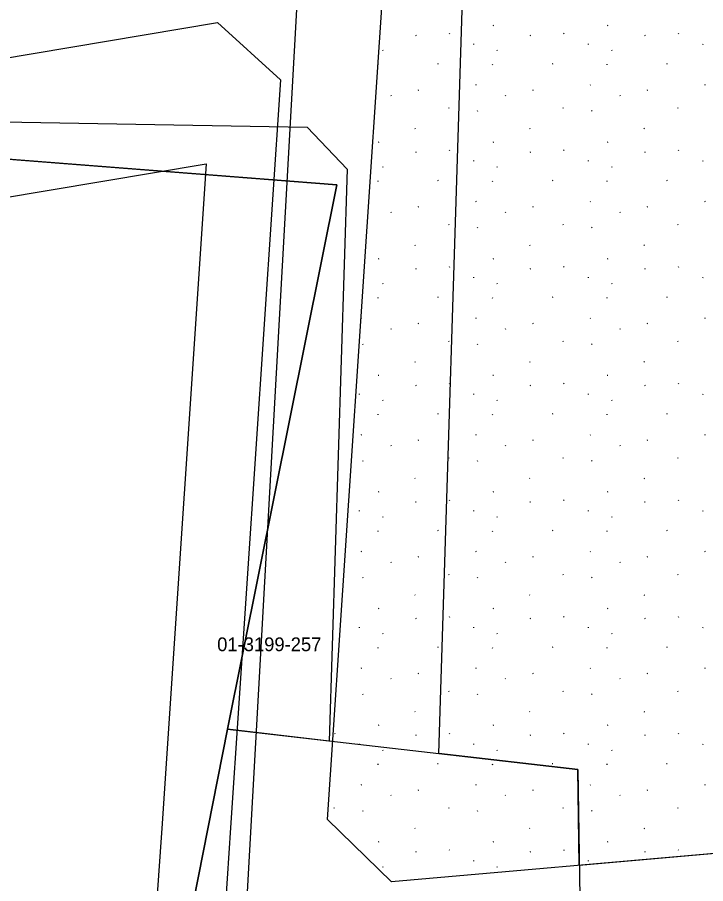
# Model space of a CAD drawing. Extents: x 419396 to 421519, y 4453567 to 4456767.
# Drawn here: x 420295.9 to 420346, y 4454723.5 to 4454786.6 of the extents above; entities that cross this region are included whole.
import ezdxf

# ---------------------------------------------------------------- set-up
doc = ezdxf.new("R2010")
doc.units = 0
for name, color, linetype in [('0_KADASTRO', 7, 'Continuous'), ('Level 20', 7, 'Continuous'), ('Level 29', 7, 'Continuous'), ('Level 41', 7, 'Continuous'), ('Level 9', 7, 'Continuous')]:
    doc.layers.add(name, color=color, linetype=linetype)

msp = doc.modelspace()

# ---------------------------------------------------------------- linework, layer by layer
at = {"layer": '0_KADASTRO'}
msp.add_lwpolyline([(420581.921, 4454746.454), (420336.793, 4454724.85), (420336.68, 4454731.82), (420326.57, 4454732.983), (420328.347, 4454789.429), (420328.423, 4454790.086), (420328.605, 4454790.721), (420328.89, 4454791.318), (420329.268, 4454791.859), (420329.731, 4454792.331), (420330.266, 4454792.72), (420330.857, 4454793.016), (420331.488, 4454793.21), (420432.926, 4454815.455)], dxfattribs=at)
for points in [[(420234.94, 4454775.21), (420237.99, 4454775.74), (420244.42, 4454776.89), (420251.07, 4454778.12), (420256.763, 4454779.251), (420319.17, 4454774.37), (420311.2, 4454734.75), (420308.37, 4454720.37), (420303.03, 4454697.63), (420301.63, 4454668.31), (420262.04, 4454668.65), (420253.019, 4454668.718), (420240.25, 4454669.24), (420238.25, 4454709.08), (420234.96, 4454774.88)], [(420268.759, 4454778.312), (420269.91, 4454779.388), (420317.003, 4454778.579), (420319.904, 4454775.525), (420318.591, 4454733.9), (420311.2, 4454734.75), (420319.17, 4454774.37)], [(420303.03, 4454697.63), (420308.37, 4454720.37), (420311.2, 4454734.75), (420336.68, 4454731.82), (420337.21, 4454699.26), (420323.81, 4454697.51), (420311.24, 4454697.29)]]:
    msp.add_lwpolyline(points, close=True, dxfattribs=at)
at = {"layer": 'Level 20'}
for p, q in [((420245.029, 4454765.083), (420309.65, 4454775.903)), ((420309.65, 4454775.903), (420306.439, 4454727.908)), ((420306.439, 4454727.908), (420305.299, 4454710.862))]:
    msp.add_line(p, q, dxfattribs=at)
at = {"layer": 'Level 29'}
for p, q in [((420318.485, 4454728.196), (420322.518, 4454788.474)), ((420241.237, 4454774.587), (420310.473, 4454786.18)), ((420310.473, 4454786.18), (420315.071, 4454782.017)), ((420315.071, 4454782.017), (420311.428, 4454727.574)), ((420426.15, 4454732.726), (420323.132, 4454723.646)), ((420323.132, 4454723.646), (420318.485, 4454728.196)), ((420311.428, 4454727.574), (420310.287, 4454710.528))]:
    msp.add_line(p, q, dxfattribs=at)
at = {"layer": 'Level 41'}
for p, q in [((420330.549, 4454785.976), (420330.502, 4454785.953)), ((420338.881, 4454785.976), (420338.834, 4454785.953)), ((420324.92, 4454785.247), (420324.873, 4454785.224)), ((420327.328, 4454785.411), (420327.356, 4454785.367)), ((420333.252, 4454785.247), (420333.205, 4454785.224)), ((420335.66, 4454785.411), (420335.688, 4454785.367)), ((420341.584, 4454785.247), (420341.537, 4454785.224)), ((420343.993, 4454785.411), (420344.021, 4454785.367)), ((420329.128, 4454784.582), (420329.135, 4454784.633)), ((420337.46, 4454784.582), (420337.467, 4454784.633)), ((420345.792, 4454784.582), (420345.8, 4454784.633)), ((420322.469, 4454784.196), (420322.497, 4454784.152)), ((420330.801, 4454784.196), (420330.829, 4454784.152)), ((420339.133, 4454784.196), (420339.161, 4454784.152)), ((420322.162, 4454783.108), (420322.17, 4454783.159)), ((420326.529, 4454783.182), (420326.482, 4454783.159)), ((420330.494, 4454783.108), (420330.502, 4454783.159)), ((420334.861, 4454783.182), (420334.815, 4454783.159)), ((420338.827, 4454783.108), (420338.834, 4454783.159)), ((420343.194, 4454783.182), (420343.147, 4454783.159)), ((420325.102, 4454781.253), (420325.055, 4454781.23)), ((420329.293, 4454781.648), (420329.246, 4454781.625)), ((420333.434, 4454781.253), (420333.387, 4454781.23)), ((420337.625, 4454781.648), (420337.578, 4454781.625)), ((420341.766, 4454781.253), (420341.719, 4454781.23)), ((420345.957, 4454781.648), (420345.91, 4454781.625)), ((420323.076, 4454780.9), (420323.104, 4454780.857)), ((420331.408, 4454780.9), (420331.437, 4454780.857)), ((420339.741, 4454780.9), (420339.769, 4454780.857)), ((420327.274, 4454779.997), (420327.302, 4454779.953)), ((420335.606, 4454779.997), (420335.634, 4454779.953)), ((420343.938, 4454779.997), (420343.966, 4454779.953)), ((420329.363, 4454779.777), (420329.391, 4454779.733)), ((420337.695, 4454779.777), (420337.723, 4454779.733)), ((420324.838, 4454778.501), (420324.866, 4454778.457)), ((420333.17, 4454778.501), (420333.198, 4454778.457)), ((420341.502, 4454778.501), (420341.53, 4454778.457)), ((420322.217, 4454777.488), (420322.17, 4454777.465)), ((420330.549, 4454777.488), (420330.502, 4454777.465)), ((420338.881, 4454777.488), (420338.834, 4454777.465)), ((420324.92, 4454776.759), (420324.873, 4454776.736)), ((420327.328, 4454776.922), (420327.356, 4454776.878)), ((420333.252, 4454776.759), (420333.205, 4454776.736)), ((420335.66, 4454776.922), (420335.688, 4454776.878)), ((420341.584, 4454776.759), (420341.537, 4454776.736)), ((420343.993, 4454776.922), (420344.021, 4454776.878)), ((420329.128, 4454776.093), (420329.135, 4454776.144)), ((420337.46, 4454776.093), (420337.467, 4454776.144)), ((420345.792, 4454776.093), (420345.8, 4454776.144)), ((420322.469, 4454775.707), (420322.497, 4454775.663)), ((420330.801, 4454775.707), (420330.829, 4454775.663)), ((420339.133, 4454775.707), (420339.161, 4454775.663)), ((420322.162, 4454774.619), (420322.17, 4454774.671)), ((420326.529, 4454774.694), (420326.482, 4454774.671)), ((420330.494, 4454774.619), (420330.502, 4454774.671)), ((420334.861, 4454774.694), (420334.815, 4454774.671)), ((420338.827, 4454774.619), (420338.834, 4454774.671)), ((420343.194, 4454774.694), (420343.147, 4454774.671)), ((420329.293, 4454773.159), (420329.246, 4454773.137)), ((420337.625, 4454773.159), (420337.578, 4454773.137)), ((420345.957, 4454773.159), (420345.91, 4454773.137)), ((420323.076, 4454772.412), (420323.104, 4454772.368)), ((420325.102, 4454772.764), (420325.055, 4454772.742)), ((420331.408, 4454772.412), (420331.437, 4454772.368)), ((420333.434, 4454772.764), (420333.387, 4454772.742)), ((420339.741, 4454772.412), (420339.769, 4454772.368)), ((420341.766, 4454772.764), (420341.719, 4454772.742)), ((420327.274, 4454771.508), (420327.302, 4454771.465)), ((420329.363, 4454771.288), (420329.391, 4454771.244)), ((420335.606, 4454771.508), (420335.634, 4454771.465)), ((420337.695, 4454771.288), (420337.723, 4454771.244)), ((420343.938, 4454771.508), (420343.966, 4454771.465)), ((420324.838, 4454770.012), (420324.866, 4454769.969)), ((420333.17, 4454770.012), (420333.198, 4454769.969)), ((420341.502, 4454770.012), (420341.53, 4454769.969)), ((420322.217, 4454768.999), (420322.17, 4454768.976)), ((420330.549, 4454768.999), (420330.502, 4454768.976)), ((420338.881, 4454768.999), (420338.834, 4454768.976)), ((420324.92, 4454768.27), (420324.873, 4454768.247)), ((420327.328, 4454768.433), (420327.356, 4454768.389)), ((420333.252, 4454768.27), (420333.205, 4454768.247)), ((420335.66, 4454768.433), (420335.688, 4454768.389)), ((420341.584, 4454768.27), (420341.537, 4454768.247)), ((420343.993, 4454768.433), (420344.021, 4454768.389)), ((420329.128, 4454767.604), (420329.135, 4454767.655)), ((420337.46, 4454767.604), (420337.467, 4454767.655)), ((420345.792, 4454767.604), (420345.8, 4454767.655)), ((420322.469, 4454767.218), (420322.497, 4454767.175)), ((420330.801, 4454767.218), (420330.829, 4454767.175)), ((420339.133, 4454767.218), (420339.161, 4454767.175)), ((420322.162, 4454766.131), (420322.17, 4454766.182)), ((420326.529, 4454766.205), (420326.482, 4454766.182)), ((420330.494, 4454766.131), (420330.502, 4454766.182)), ((420334.861, 4454766.205), (420334.815, 4454766.182)), ((420338.827, 4454766.131), (420338.834, 4454766.182)), ((420343.194, 4454766.205), (420343.147, 4454766.182)), ((420320.961, 4454764.671), (420320.924, 4454764.653)), ((420325.102, 4454764.276), (420325.055, 4454764.253)), ((420329.293, 4454764.671), (420329.246, 4454764.648)), ((420333.434, 4454764.276), (420333.387, 4454764.253)), ((420337.625, 4454764.671), (420337.578, 4454764.648)), ((420341.766, 4454764.276), (420341.719, 4454764.253)), ((420345.957, 4454764.671), (420345.91, 4454764.648)), ((420323.076, 4454763.923), (420323.104, 4454763.879)), ((420331.408, 4454763.923), (420331.437, 4454763.879)), ((420339.741, 4454763.923), (420339.769, 4454763.879)), ((420327.274, 4454763.019), (420327.302, 4454762.976)), ((420335.606, 4454763.019), (420335.634, 4454762.976)), ((420343.938, 4454763.019), (420343.966, 4454762.976)), ((420321.031, 4454762.799), (420321.059, 4454762.755)), ((420329.363, 4454762.799), (420329.391, 4454762.755)), ((420337.695, 4454762.799), (420337.723, 4454762.755)), ((420324.838, 4454761.523), (420324.866, 4454761.48)), ((420333.17, 4454761.523), (420333.198, 4454761.48)), ((420341.502, 4454761.523), (420341.53, 4454761.48)), ((420322.217, 4454760.51), (420322.17, 4454760.487)), ((420330.549, 4454760.51), (420330.502, 4454760.487)), ((420338.881, 4454760.51), (420338.834, 4454760.487)), ((420324.92, 4454759.781), (420324.873, 4454759.758)), ((420327.328, 4454759.944), (420327.356, 4454759.901)), ((420333.252, 4454759.781), (420333.205, 4454759.758)), ((420335.66, 4454759.944), (420335.688, 4454759.901)), ((420341.584, 4454759.781), (420341.537, 4454759.758)), ((420343.993, 4454759.944), (420344.021, 4454759.901)), ((420320.796, 4454759.115), (420320.803, 4454759.166)), ((420329.128, 4454759.115), (420329.135, 4454759.166)), ((420337.46, 4454759.115), (420337.467, 4454759.166)), ((420345.792, 4454759.115), (420345.8, 4454759.166)), ((420322.469, 4454758.729), (420322.497, 4454758.686)), ((420330.801, 4454758.729), (420330.829, 4454758.686)), ((420339.133, 4454758.729), (420339.161, 4454758.686)), ((420322.162, 4454757.642), (420322.17, 4454757.693)), ((420326.529, 4454757.716), (420326.482, 4454757.693)), ((420330.494, 4454757.642), (420330.502, 4454757.693)), ((420334.861, 4454757.716), (420334.815, 4454757.693)), ((420338.827, 4454757.642), (420338.834, 4454757.693)), ((420343.194, 4454757.716), (420343.147, 4454757.693)), ((420320.961, 4454756.182), (420320.914, 4454756.159)), ((420329.293, 4454756.182), (420329.246, 4454756.159)), ((420337.625, 4454756.182), (420337.578, 4454756.159)), ((420345.957, 4454756.182), (420345.91, 4454756.159)), ((420323.076, 4454755.434), (420323.104, 4454755.39)), ((420325.102, 4454755.787), (420325.055, 4454755.764)), ((420331.408, 4454755.434), (420331.437, 4454755.39)), ((420333.434, 4454755.787), (420333.387, 4454755.764)), ((420339.741, 4454755.434), (420339.769, 4454755.39)), ((420341.766, 4454755.787), (420341.719, 4454755.764)), ((420321.031, 4454754.31), (420321.059, 4454754.266)), ((420327.274, 4454754.531), (420327.302, 4454754.487)), ((420329.363, 4454754.31), (420329.391, 4454754.266)), ((420335.606, 4454754.531), (420335.634, 4454754.487)), ((420337.695, 4454754.31), (420337.723, 4454754.266)), ((420343.938, 4454754.531), (420343.966, 4454754.487)), ((420324.838, 4454753.035), (420324.866, 4454752.991)), ((420333.17, 4454753.035), (420333.198, 4454752.991)), ((420341.502, 4454753.035), (420341.53, 4454752.991)), ((420322.217, 4454752.021), (420322.17, 4454751.998)), ((420330.549, 4454752.021), (420330.502, 4454751.998)), ((420338.881, 4454752.021), (420338.834, 4454751.998)), ((420324.92, 4454751.292), (420324.873, 4454751.269)), ((420327.328, 4454751.455), (420327.356, 4454751.412)), ((420333.252, 4454751.292), (420333.205, 4454751.269)), ((420335.66, 4454751.455), (420335.688, 4454751.412)), ((420341.584, 4454751.292), (420341.537, 4454751.269)), ((420343.993, 4454751.455), (420344.021, 4454751.412)), ((420320.796, 4454750.626), (420320.803, 4454750.678)), ((420322.469, 4454750.241), (420322.497, 4454750.197)), ((420329.128, 4454750.626), (420329.135, 4454750.678)), ((420330.801, 4454750.241), (420330.829, 4454750.197)), ((420337.46, 4454750.626), (420337.467, 4454750.678)), ((420339.133, 4454750.241), (420339.161, 4454750.197)), ((420345.792, 4454750.626), (420345.8, 4454750.678)), ((420322.162, 4454749.153), (420322.17, 4454749.204)), ((420326.529, 4454749.227), (420326.482, 4454749.204)), ((420330.494, 4454749.153), (420330.502, 4454749.204)), ((420334.861, 4454749.227), (420334.815, 4454749.204)), ((420338.827, 4454749.153), (420338.834, 4454749.204)), ((420343.194, 4454749.227), (420343.147, 4454749.204)), ((420320.961, 4454747.693), (420320.914, 4454747.67)), ((420329.293, 4454747.693), (420329.246, 4454747.67)), ((420337.625, 4454747.693), (420337.578, 4454747.67)), ((420345.957, 4454747.693), (420345.91, 4454747.67)), ((420325.102, 4454747.298), (420325.055, 4454747.275)), ((420333.434, 4454747.298), (420333.387, 4454747.275)), ((420341.766, 4454747.298), (420341.719, 4454747.275)), ((420323.076, 4454746.945), (420323.104, 4454746.901)), ((420331.408, 4454746.945), (420331.437, 4454746.901)), ((420339.741, 4454746.945), (420339.769, 4454746.901)), ((420321.031, 4454745.821), (420321.059, 4454745.778)), ((420327.274, 4454746.042), (420327.302, 4454745.998)), ((420329.363, 4454745.821), (420329.391, 4454745.778)), ((420335.606, 4454746.042), (420335.634, 4454745.998)), ((420337.695, 4454745.821), (420337.723, 4454745.778)), ((420343.938, 4454746.042), (420343.966, 4454745.998)), ((420324.838, 4454744.546), (420324.866, 4454744.502)), ((420333.17, 4454744.546), (420333.198, 4454744.502)), ((420341.502, 4454744.546), (420341.53, 4454744.502)), ((420322.217, 4454743.532), (420322.17, 4454743.509)), ((420330.549, 4454743.532), (420330.502, 4454743.509)), ((420338.881, 4454743.532), (420338.834, 4454743.509)), ((420324.92, 4454742.803), (420324.873, 4454742.78)), ((420327.328, 4454742.967), (420327.356, 4454742.923)), ((420333.252, 4454742.803), (420333.205, 4454742.78)), ((420335.66, 4454742.967), (420335.688, 4454742.923)), ((420341.584, 4454742.803), (420341.537, 4454742.78)), ((420343.993, 4454742.967), (420344.021, 4454742.923)), ((420320.796, 4454742.138), (420320.803, 4454742.189)), ((420329.128, 4454742.138), (420329.135, 4454742.189)), ((420337.46, 4454742.138), (420337.467, 4454742.189)), ((420345.792, 4454742.138), (420345.8, 4454742.189)), ((420322.469, 4454741.752), (420322.497, 4454741.708)), ((420330.801, 4454741.752), (420330.829, 4454741.708)), ((420339.133, 4454741.752), (420339.161, 4454741.708)), ((420322.162, 4454740.664), (420322.17, 4454740.715)), ((420326.529, 4454740.738), (420326.482, 4454740.715)), ((420330.494, 4454740.664), (420330.502, 4454740.715)), ((420334.861, 4454740.738), (420334.815, 4454740.715)), ((420338.827, 4454740.664), (420338.834, 4454740.715)), ((420343.194, 4454740.738), (420343.147, 4454740.715)), ((420320.961, 4454739.204), (420320.914, 4454739.181)), ((420329.293, 4454739.204), (420329.246, 4454739.181)), ((420337.625, 4454739.204), (420337.578, 4454739.181)), ((420345.957, 4454739.204), (420345.91, 4454739.181)), ((420323.076, 4454738.456), (420323.104, 4454738.413)), ((420325.102, 4454738.809), (420325.055, 4454738.786)), ((420331.408, 4454738.456), (420331.437, 4454738.413)), ((420333.434, 4454738.809), (420333.387, 4454738.786)), ((420339.741, 4454738.456), (420339.769, 4454738.413)), ((420341.766, 4454738.809), (420341.719, 4454738.786)), ((420321.031, 4454737.333), (420321.059, 4454737.289)), ((420327.274, 4454737.553), (420327.302, 4454737.509)), ((420329.363, 4454737.333), (420329.391, 4454737.289)), ((420335.606, 4454737.553), (420335.634, 4454737.509)), ((420337.695, 4454737.333), (420337.723, 4454737.289)), ((420343.938, 4454737.553), (420343.966, 4454737.509)), ((420324.838, 4454736.057), (420324.866, 4454736.013)), ((420333.17, 4454736.057), (420333.198, 4454736.013)), ((420341.502, 4454736.057), (420341.53, 4454736.013)), ((420318.996, 4454734.478), (420319.024, 4454734.434)), ((420322.217, 4454735.044), (420322.17, 4454735.021)), ((420327.328, 4454734.478), (420327.356, 4454734.434)), ((420330.549, 4454735.044), (420330.502, 4454735.021)), ((420335.66, 4454734.478), (420335.688, 4454734.434)), ((420338.881, 4454735.044), (420338.834, 4454735.021)), ((420343.993, 4454734.478), (420344.021, 4454734.434)), ((420324.92, 4454734.315), (420324.873, 4454734.292)), ((420333.252, 4454734.315), (420333.205, 4454734.292)), ((420341.584, 4454734.315), (420341.537, 4454734.292)), ((420320.796, 4454733.649), (420320.803, 4454733.7)), ((420322.469, 4454733.263), (420322.497, 4454733.219)), ((420329.128, 4454733.649), (420329.135, 4454733.7)), ((420330.801, 4454733.263), (420330.829, 4454733.219)), ((420337.46, 4454733.649), (420337.467, 4454733.7)), ((420339.133, 4454733.263), (420339.161, 4454733.219)), ((420345.792, 4454733.649), (420345.8, 4454733.7)), ((420322.162, 4454732.175), (420322.17, 4454732.227)), ((420326.529, 4454732.25), (420326.482, 4454732.227)), ((420330.494, 4454732.175), (420330.502, 4454732.227)), ((420334.861, 4454732.25), (420334.815, 4454732.227)), ((420338.827, 4454732.175), (420338.834, 4454732.227)), ((420343.194, 4454732.25), (420343.147, 4454732.227)), ((420320.961, 4454730.715), (420320.914, 4454730.693)), ((420329.293, 4454730.715), (420329.246, 4454730.693)), ((420337.625, 4454730.715), (420337.578, 4454730.693)), ((420345.957, 4454730.715), (420345.91, 4454730.693)), ((420325.102, 4454730.32), (420325.055, 4454730.298)), ((420333.434, 4454730.32), (420333.387, 4454730.298)), ((420341.766, 4454730.32), (420341.719, 4454730.298)), ((420323.076, 4454729.968), (420323.104, 4454729.924)), ((420331.408, 4454729.968), (420331.437, 4454729.924)), ((420339.741, 4454729.968), (420339.769, 4454729.924)), ((420318.942, 4454729.064), (420318.97, 4454729.021)), ((420321.031, 4454728.844), (420321.059, 4454728.8)), ((420327.274, 4454729.064), (420327.302, 4454729.021)), ((420329.363, 4454728.844), (420329.391, 4454728.8)), ((420335.606, 4454729.064), (420335.634, 4454729.021)), ((420337.695, 4454728.844), (420337.723, 4454728.8)), ((420343.938, 4454729.064), (420343.966, 4454729.021)), ((420324.838, 4454727.568), (420324.866, 4454727.525)), ((420333.17, 4454727.568), (420333.198, 4454727.525)), ((420341.502, 4454727.568), (420341.53, 4454727.525)), ((420322.217, 4454726.555), (420322.17, 4454726.532)), ((420330.549, 4454726.555), (420330.502, 4454726.532)), ((420338.881, 4454726.555), (420338.834, 4454726.532)), ((420324.92, 4454725.826), (420324.873, 4454725.803)), ((420327.328, 4454725.989), (420327.356, 4454725.945)), ((420333.252, 4454725.826), (420333.205, 4454725.803)), ((420335.66, 4454725.989), (420335.688, 4454725.945)), ((420341.584, 4454725.826), (420341.537, 4454725.803)), ((420343.993, 4454725.989), (420344.021, 4454725.945)), ((420329.128, 4454725.16), (420329.135, 4454725.211)), ((420337.46, 4454725.16), (420337.467, 4454725.211)), ((420322.469, 4454724.774), (420322.497, 4454724.731)), ((420330.801, 4454724.774), (420330.829, 4454724.731))]:
    msp.add_line(p, q, dxfattribs=at)
at = {"layer": 'Level 9'}
msp.add_line((420316.894, 4454799.204), (420311.704, 4454706.433), dxfattribs=at)

# ---------------------------------------------------------------- texts
at = {"layer": '0_KADASTRO'}
msp.add_text('01-3199-257', height=1, dxfattribs=at).set_placement((420310.453, 4454740.437))

doc.saveas('drawing.dxf')
